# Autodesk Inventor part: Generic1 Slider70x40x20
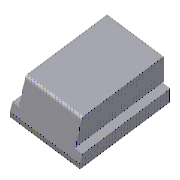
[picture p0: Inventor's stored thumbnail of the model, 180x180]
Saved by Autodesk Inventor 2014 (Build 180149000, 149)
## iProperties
IsCustomPart: 1
Created: 2009-11
Part Number: Generic1 Slider70x40x20
Material: DIN 1.2343
Description: Slider
Document SubType Name: Modeling
Designer: gaom
Standard Revision: 1
Manufacturer: Generic
Language: en-US
Size Designation: 70x40x20
Categories: <MemberInstance><Categories><Category DisplayName="Mold" InternalName="349578f2-f4d4-4954-8c09-8e99297a61c0" Mnemonic="MOLD"><Category DisplayName="Slide Compon
Density: 7.85 g/cm^3
Appearance: Sky Blue Dark
Author: gaom
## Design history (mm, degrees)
sketch "Sketch1"
  geometry: L1 (0, -24)-(0, 4) reference; L2 (0, 0)-(-20, 0); L3 (-20, 0)-(-20, -15.5); L4 (-20, -15.5)-(-19.5, -15.5); L5 (-19.5, -15.5)-(-19.5, -16); L6 (-19.5, -16)-(-24.5, -16); L7 (-24.5, -16)-(-24.5, -20); L8 (-24.5, -20)-(0, -20); L9 (0, 0)-(20, 0); L10 (20, 0)-(20, -15.5); L11 (20, -15.5)-(19.5, -15.5); L12 (19.5, -15.5)-(19.5, -16); L13 (19.5, -16)-(24.5, -16); L14 (24.5, -16)-(24.5, -20); L15 (24.5, -20)-(0, -20)
  constraints: 28 end point, 6 symmetric about line, 4 parallel, 3 perpendicular, 1 point on line
  dimensions: "d1" = 40 diameter of L3 L1 (= SL_b1); "d2" = 20 distance between parallel lines of L8 L2 (= SL_h1); "d3" = 49 diameter of L7 L1 (= SL_b2); "d4" = 0.5 distance of L4.end L5.end (= REF_SL1); "d5" = 0.5 distance of L3.end L4.end (= REF_SL1); "d6" = 4 distance between parallel lines of L8 L6 (= SL_h2)
extrude "Extrusion1" new body sketch "Sketch1" distance "d7" = 70 (= SL_l1); taper "d8" = 0 deg
sketch "Sketch2"
  geometry: L1 (-70, -20)-(-70, -16) reference; L2 (-70, -18.5)-(-63.267, 0); L3 (-70, -15.5)-(-70, 0) reference; L4 (0, 0)-(-70, 0) reference; L5 (-70, -18.5)-(-70, 0); L6 (-70, 0)-(-63.267, 0)
  constraints: 6 end point, 2 point on line, 1 collinear, 1 perpendicular
  dimensions: "d9" = 20 deg angle of L3 L2 (= SL_ang); "d10" = 1.5 distance of L1.start L2.start (= SL_h3)
extrude "Extrusion2" cut sketch "Sketch2" stored distance "d11" = 49 (= SL_b2); taper "d12" = 0 deg
fillet "Fillet1" dims "d123" = 0.5 (= REF_SL1)
node "SL_AP"
node "SL_GS"
node "SL_GSl"
node "SL_GSr"
node "SL_SP"
node "SL_WP"
feature "Sculpt6"
body "Solid1"
fillet "Fillet2" dims "d125" = 1.5 (= SL_r)
feature "Stitch Surface1" dims "d124" = 0.254 (derived)
workplane "Work Plane1"
sketch "Sketch3"
  geometry: L1 (-16, -24.5)-(-20, -24.5); L2 (-20, 0)-(-20, 25); L3 (-20, 25)-(-16, 25); L4 (-16, 25)-(-16, 21); L5 (-16, 21)-(0, 21); L6 (0, 21)-(0, -0.659); L7 (-14.748, 0)-(3.452, 0); L8 (-20, 0)-(-20, -25); L9 (-20, -25)-(-16, -25); L10 (-16, -25)-(-16, -21); L11 (-16, -21)-(0, -21); L12 (0, -21)-(0, -0.659); L13 (-20, 24.5)-(-16, 24.5) reference; L14 (-15.5, 20)-(0, 20) reference; L15 (0, 20)-(0, -20) reference; L16 (-20, -24.5)-(-20, 24.5) reference; L17 (-16, 24.5)-(-16, 19.5) reference; 3 further points
  constraints: 24 end point, 4 symmetric about line, 3 midpoint, 2 perpendicular, 2 point on line, 2 vertical
  dimensions: "d112" = 0.5 distance between parallel lines of L13 L3 (= REF_SL1); "d113" = 1 distance between parallel lines of L14 L5 (= REF_SL3); "d114" = 0 distance between parallel lines of L6 L15
body "Srf1"
body "Srf2"
body "Srf3"
body "Srf4"
extrude_surface "ExtrusionSrf1" dims "d90" = 170 (= SL_esl1 + SL_l1), "d91" = 0
patch "Boundary Patch1" dims "d100" = 0, "d115" = 0, "d116" = 0, "d117" = 0, "d118" = 0, "d119" = 0, "d120" = 0, "d121" = 0, "d122" = 0
patch "Boundary Patch2" dims "d101" = 0, "d102" = 0, "d103" = 0, "d104" = 0, "d105" = 0, "d106" = 0, "d107" = 0, "d108" = 0, "d109" = 0
feature "Surface6"
body "Srf10"
other parameters: "SL_ang" = 20 deg [user parameter; used in 1 equation term], "SL_h1" = 20 [user parameter; used in 1 equation term], "SL_l1" = 70 [user parameter; used in 3 equation terms], "SL_b1" = 40 [user parameter; used in 1 equation term], "SL_h2" = 4 [user parameter; used in 1 equation term], "SL_h3" = 1.5 [user parameter; used in 1 equation term], "SL_b2" = 49 [user parameter; used in 2 equation terms], "SL_r" = 1.5 [user parameter; used in 1 equation term], "SL_AP_ang" = 3.14159 [user parameter; used in 1 equation term], "d62" = 0, "d64" = 0, "d66" = 180 deg, "d67" = 3.14159 (= SL_AP_ang), "d68" = 35 (= 0.5 x SL_l1), "d70" = 180 deg, "d71" = 0, "SL_esr" = 2.5 [user parameter], "SL_esl1" = 100 [user parameter; used in 1 equation term], "REF_SL1" = 0.5 [user parameter; used in 4 equation terms], "REF_SL2" = 1 [user parameter], "REF_SL3" = 1 [user parameter; used in 1 equation term]
